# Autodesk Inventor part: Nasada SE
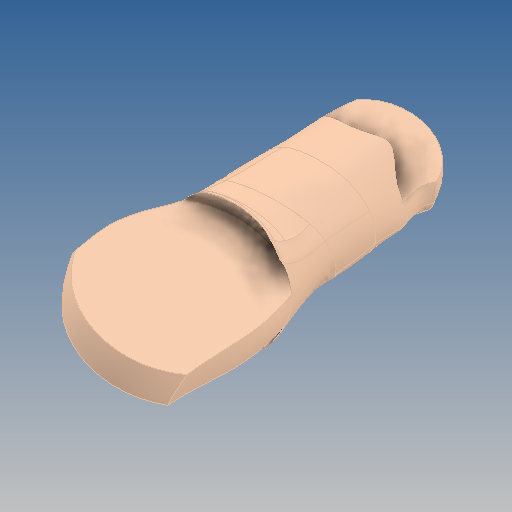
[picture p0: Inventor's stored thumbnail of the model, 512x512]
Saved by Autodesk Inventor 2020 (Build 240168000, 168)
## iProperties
Created: 2019-10
Part Number: Nasada SE
Material: GFRP
Document SubType Name: Modeling
Designer: yello
Density: 1.75 g/cm^3
Appearance: Default
Author: yello
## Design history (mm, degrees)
feature "Nasada SE"
body "Solid1"
